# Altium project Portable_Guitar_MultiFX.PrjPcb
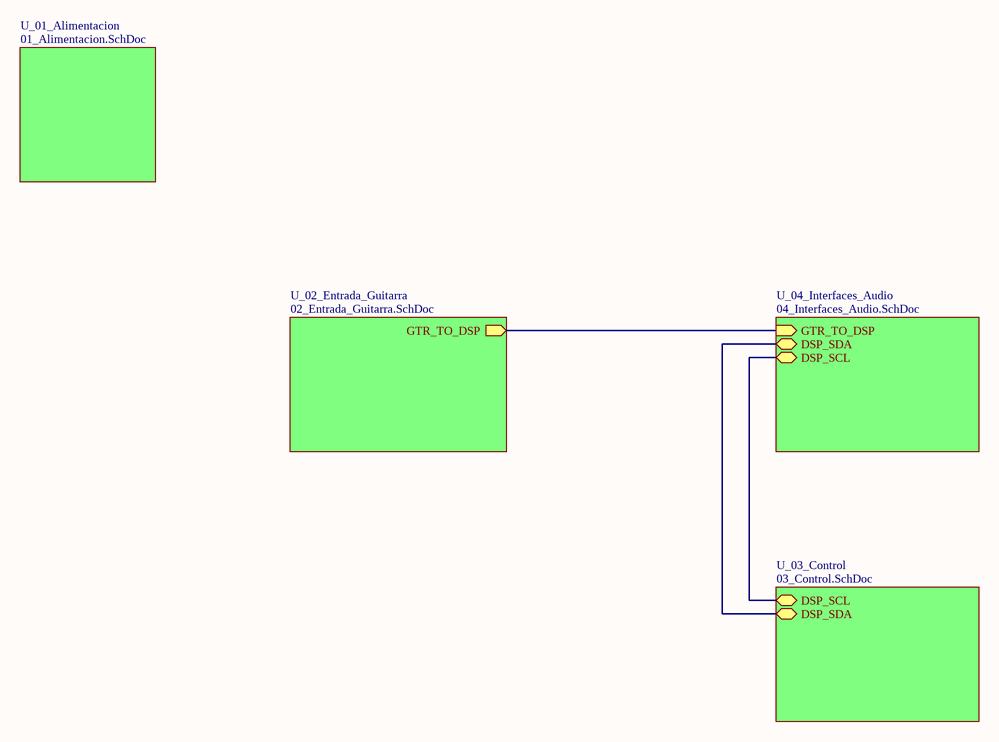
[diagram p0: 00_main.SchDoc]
5 sheets, 67 parts. Net scope: hierarchical (ports join the sheet entries above them; power ports are global).
Board file: Portable_Guitar_MultiFX.PcbDoc
Sheets:
  00_main.SchDoc
    U_02_Entrada_Guitarra = 02_Entrada_Guitarra.SchDoc
    U_04_Interfaces_Audio = 04_Interfaces_Audio.SchDoc
    U_03_Control = 03_Control.SchDoc
    U_01_Alimentacion = 01_Alimentacion.SchDoc

## Sheet 00_main.SchDoc: Portable_Guitar_MultiFX
size A4; Author: Javier Estiven Leon Calderon; Organization: Altium Limited; Address1: L3, 12a Rodborough Rd; Address2: Frenchs Forest; Address3: NSW; Address4: Australia 2086; DocumentNumber: 1; Revision: 1.0; SheetNumber: 1; SheetTotal: 5

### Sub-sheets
U_01_Alimentacion = 01_Alimentacion.SchDoc: no entries
U_02_Entrada_Guitarra = 02_Entrada_Guitarra.SchDoc: GTR_TO_DSP (out)
U_03_Control = 03_Control.SchDoc: DSP_SCL (bidir), DSP_SDA (bidir)
U_04_Interfaces_Audio = 04_Interfaces_Audio.SchDoc: GTR_TO_DSP (in), DSP_SDA (bidir), DSP_SCL (bidir)

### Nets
NetC8_2: sheet U_02_Entrada_Guitarra/GTR_TO_DSP, sheet U_04_Interfaces_Audio/GTR_TO_DSP
NetJP4_2: sheet U_04_Interfaces_Audio/DSP_SCL, sheet U_03_Control/DSP_SCL
NetJP5_2: sheet U_04_Interfaces_Audio/DSP_SDA, sheet U_03_Control/DSP_SDA

## Sheet 02_Entrada_Guitarra.SchDoc: Portable_Guitar_MultiFX
size A4; Organization: Altium Limited; Address1: L3, 12a Rodborough Rd; Address2: Frenchs Forest; Address3: NSW; Address4: Australia 2086; DocumentNumber: 1; Revision: 1.0; SheetNumber: 3; SheetTotal: 5; SPICEModelCachePUIILNWP: <root> / <DocumentId>PUIILNWP</DocumentId> / <CacheFrame Number="0"> / <Model Name="mcp6001" Kind="CKT"> / <Text>.SUBCKT MCP6001 1 2 3 4 5 / *               ¦ ¦ ¦ ¦ ¦ / *               ¦ ¦ ¦ ¦ Output / *               ¦ ¦ ¦ Negative Supply / *               ¦ ¦ Positive Supply / *               ¦ Inverting Input / *               Non-inverting Input / * / ******************************************************************************** / * Software License Agreement                                                   * / *                                                                              * / * The software supplied herewith by Microchip Technology Incorporated (the     * / * "Company") is intended and supplied to you, the Company's customer, for use  * / * soley and exclusively on Microchip products.                                 * / *                                                                              * / * The software is owned by the Company and/or its supplier, and is protected   * / * under applicable copyright laws. All rights are reserved. Any use in         * / * violation of the foregoing restrictions may subject the user to criminal     * / * sanctions under applicable laws, as well as to civil liability for the       * / * breach of the terms and conditions of this license.                          * / *                                                                              * / * THIS SOFTWARE IS PROVIDED IN AN "AS IS" CONDITION. NO WARRANTIES, WHETHER    * / * EXPRESS, IMPLIED OR STATUTORY, INCLUDING, BUT NOT LIMITED TO, IMPLIED        * / * WARRANTIES OF MERCHANTABILITY AND FITNESS FOR A PARTICULAR PURPOSE APPLY TO  * / * THIS SOFTWARE. THE COMPANY SHALL NOT, IN ANY CIRCUMSTANCES, BE LIABLE FOR    * / * SPECIAL, INCIDENTAL OR CONSEQUENTIAL DAMAGES, FOR ANY REASON WHATSOEVER.     * / ******************************************************************************** / * / * Macromodel for the MCP6001/2/4 op amp family: / *   MCP6001, MCP6001R, MCP6001U, MCP6002, MCP6004 / * / * Revision History: / *   REV A: 21-Jun-02, Created model / *   REV B: 16-Jul-02, Improved output stage / *   REV C: 03-Jan-03, Added MCP6001 / *   REV D: 19-Aug-06, Added over temperature, improved output stage, / *                     fixed overdrive recovery time / *   REV E: 27-Jul-07, Updated output impedance for better model stability w/cap load / *   REV F: 09-Jul-12, Added MCP6001R, MCP6001U / * / * Recommendations: / *   Use PSPICE (other simulators may require translation) / *   For a quick, effective design, use a combination of: data sheet / *     specs, bench testing, and simulations with this macromodel / *   For high impedance circuits, set GMIN=100F in .OPTIONS / * / * Supported: / *   Typical performance for temperature range (-40 to 125) degrees Celsius / *   DC, AC, Transient, and Noise analyses. / *   Most specs, including: offsets, DC PSRR, DC CMRR, input impedance, / *     open loop gain, voltage ranges, supply current, ... , etc. / *   Temperature effects for Ibias, Iquiescent, Iout short circuit / *   current, Vsat on both rails, Slew Rate vs. Temp and P.S. / * / * Not Supported: / *   Some Variation in specs vs. Power Supply Voltage / *   Monte Carlo (Vos, Ib), Process variation / *   Distortion (detailed non-linear behavior) / *   Behavior outside normal operating region / * / * Input Stage / V10  3 10 -500M / R10 10 11 6.90K / R11 10 12 6.90K / C11 11 12 0.2p / C12 1  0 6.00P / E12 71 14 POLY(4) 20 0 21 0 26 0 27 0   1.00M 20.1 20.1 1 1 / G12 1 0 62 0 1m / M12 11 14 15 15 NMI L=2.00U W=42.0U / M14 12  2 15 15 NMI L=2.00U W=42.0U / G14 2 0 62 0 1m / C14  2  0 6.00P / I15 15  4 50.0U / V16 16  4 -300M / GD16 16 1 TABLE {V(16,1)} ((-100,-1p)(0,0)(1m,1n)(2m,1m)(3m,1)) / V13  3 13 -300M / GD13 2 13 TABLE {V(2,13)} ((-100,-1p)(0,0)(1m,1n)(2m,1m)(3m,1)) / R70 1 0 20.6T / R71 2 0 20.6T / R72 1 2 20T / I80 1 2 0.5p / * / * Noise, PSRR, and CMRR / I20 21 20 423U / D20 20  0 DN1 / D21  0 21 DN1 / G26  0 26 POLY(1) 3 4   110U -49U / R26 26  0 1 / G27  0 27 POLY(2) 1 0 2 0   -440U 39.7U 39.7U / R27 27  0 1 / * / * Open Loop Gain, Slew Rate / G30  0 30 POLY(1) 12 11   0 1 / R30 30  0 1K / G31  0 31 POLY(1) 3 4 86 5.25 / R31 31  0 1 TC=2.8m / GD31 30 31 TABLE {V(30,31)} ((-11,-1)(-10,-10n)(0,0)(1m,1000)) / G32 32  0 POLY(1) 3 4 113.7 3.5 / R32 32  0 1 TC=2.65m / GD32 30 32 TABLE {V(30,32)} ((-1m,-1000)(0,0)(10,10n)(11,1)) / G33 0 33 30 0 1m / R33 33 0 1k / G34  0 34 33 0 425M / R34  34 0 1K / C34  34 0 74U / G37  0 37 34 0 1m / R37  37 0 1K / C37  37 0 41.6P / G38  0 38 37 0 1m / R38  39 0 1K / L38  38 39 100U / E38  35 0 38 0 1 / G35 33 0 TABLE {V(35,3)} ((-1,-1n)(0,0)(16,1n))(16.1,1)) / G36 33 0 TABLE {V(35,4)} ((-16.1,-1)((-16,-1n)(0,0)(1,1n)) / * / * Output Stage / R80 50 0 100MEG / G50 0 50 57 96 2 / R58 57  96 0.50 / R57 57  0 750 / C58  5  0 2.00P / G57  0 57 POLY(3) 3 0 4 0 35 0   0 0.67M 0.67M 1.5M / GD55 55 57 TABLE {V(55,57)} ((-2m,-1)(-1m,-1m)(0,0)(10,1n)) / GD56 57 56 TABLE {V(57,56)} ((-2m,-1)(-1m,-1m)(0,0)(10,1n)) / E55 55  0 POLY(2) 3 0 51 0 -0.7m 1 -40.0M / E56 56  0 POLY(2) 4 0 52 0 1.2m 1 -37.0M / R51 51 0 1k / R52 52 0 1k / GD51 50 51 TABLE {V(50,51)} ((-10,-1n)(0,0)(1m,1m)(2m,1)) / GD52 50 52 TABLE {V(50,52)} ((-2m,-1)(-1m,-1m)(0,0)(10,1n)) / G53  3  0 POLY(1) 51 0  -49U 1M / G54  0  4 POLY(1) 52 0  -49U -1M / * / * Current Limit / G99 96 5 99 0 1 / R98 0 98 1 TC=-2.8M,2.63U / G97 0 98 TABLE { V(96,5) } ((-11.0,-10.0M)(-1.00M,-9.9M)(0,0)(1.00M,9.9M)(11.0,10.0M)) / E97 99 0 VALUE { V(98)*((V(3)-V(4))*359M + 310M)} / D98 4 5 DESD / D99 5 3 DESD / * / * Temperature / Voltage Sensitive IQuiscent / R61 0 61 100 TC 3.11M 4.51U / G61 3 4 61 0 1 / G60 0 61 TABLE {V(3, 4)} / + ((0,0)(900M,0.0106U)(1.00,0.20U)(1.3,0.63U) / + (1.5,0.66U)(1.6,1.06U)(5.5,1.10U)) / * / * Temp Sensitive offset voltage / I73 0 70 DC 1uA / R74 0 70 1 TC=2 / E75 1 71 70 0 1 / * / * Temp Sensistive IBias / I62 0 62 DC 1uA / R62 0 62 REXP 58.2u / * Voltage on R62 used for G12, G14 in input stage / * / * Models / .MODEL NMI NMOS / .MODEL DESD  D   N=1 IS=1.00E-15 / .MODEL DL  D   N=1 IS=1F / .MODEL DN1 D   IS=1P KF=146E-18 AF=1 / .MODEL REXP RES TCE=10.1 / .ENDS MCP6001</Text> / </Model> / </CacheFrame> / </root>
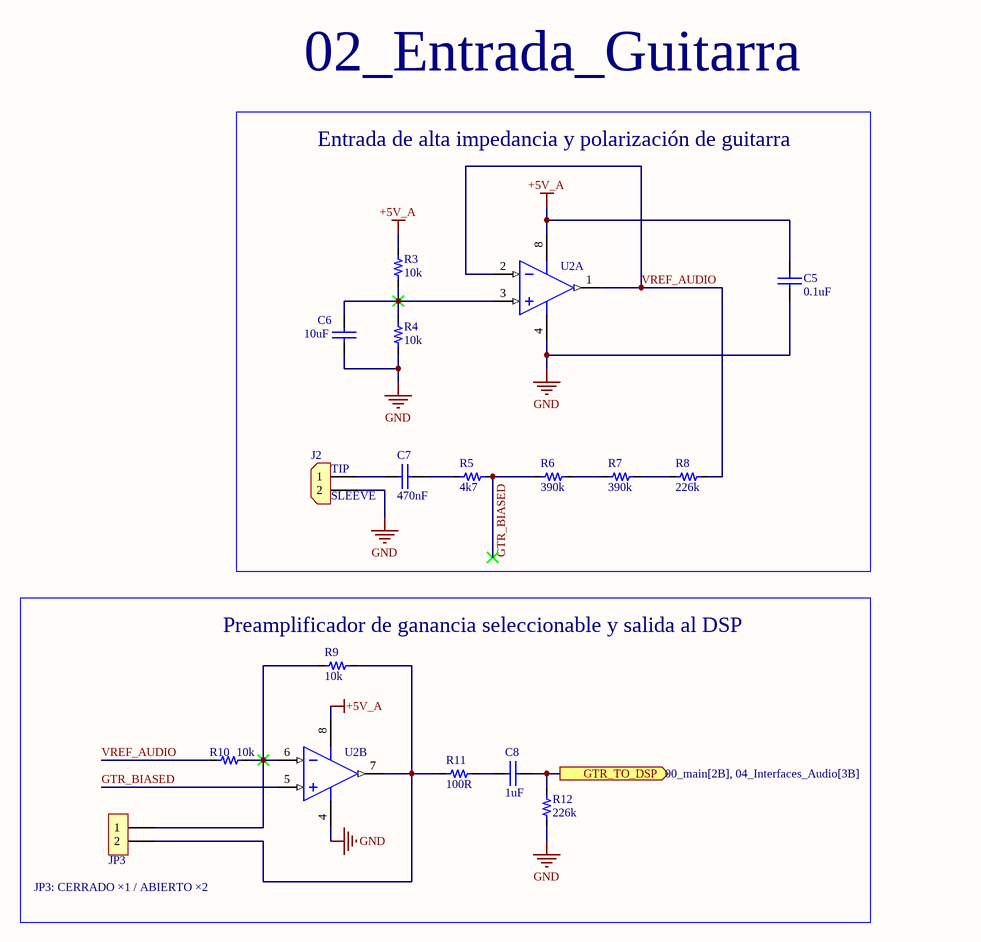
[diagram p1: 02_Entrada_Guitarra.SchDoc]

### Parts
C5  value 0.1uF  [0603_cap]  (hidden comment: 0.1uF 50V)
C6  value 10uF  [0805_cap]  (hidden comment: 10uF 25V)
C7  value 470nF  [0603_cap]  (hidden comment: 470nF 50V)
C8  value 1uF  [0603_cap]  (hidden comment: 1uF 50V)
J2  Connector 2pos  [CON_2x1_TH_5MM]  (value not drawn)
JP3  2x1  [H_2x1_TH_100mil]  (value not drawn)  (no BOM)
R3  value 10k  [0603_res]  (hidden comment: 10k 1/10W)
R4  value 10k  [0603_res]  (hidden comment: 10k 1/10W)
R5  value 4k7  [0603_res]  (hidden comment: 4k7 1/10W)
R6  value 390k  [0603_res]  (hidden comment: 390k 1/10W)
R7  value 390k  [0603_res]  (hidden comment: 390k 1/10W)
R8  value 226k  [0603_res]  (hidden comment: 226k 1/10W)
R9  value 10k  [0603_res]  (hidden comment: 10k 1/10W)
R10  value 10k  [0603_res]  (hidden comment: 10k 1/10W)
R11  value 100R  [0603_res]  (hidden comment: 100R 1/10W)
R12  value 226k  [0603_res]  (hidden comment: 226k 1/10W)
U2  MCP6002-I/P  [PDIP300-P8]  (value not drawn)  (parts A,B of 2)

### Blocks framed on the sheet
Entrada de alta impedancia y polarización de guitarra: C5-C7 J2 R3-R8 U2
Preamplificador de ganancia seleccionable y salida al DSP: C8 JP3 R9-R12 U2

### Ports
GTR_TO_DSP (out, see 00_main[2B], 04_Interfaces_Audio[3B])

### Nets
+5V_A: C5.1 R3.2 U2.8(VDD)
GND: C5.2 C6.2 J2.2 R4.1 R12.1 U2.4(VSS)
GTR_BIASED: R5.2 R6.1 U2.5(VINB+)
VREF_AUDIO: R8.2 R10.1 U2.1(VOUTA) U2.2(VINA-)
NetC6_1: C6.1 R3.1 R4.2 U2.3(VINA+)
NetC7_1: C7.1 J2.1
NetC7_2: C7.2 R5.1
NetC8_1: C8.1 R11.2
NetC8_2: C8.2 R12.2 ; port GTR_TO_DSP
NetJP3_1: JP3.1 R9.1 R10.2 U2.6(VINB-)
NetJP3_2: JP3.2 R9.2 R11.1 U2.7(VOUTB)
NetR6_2: R6.2 R7.1
NetR7_2: R7.2 R8.1

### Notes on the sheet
- 02_Entrada_Guitarra
- (near J2) TIP
- (near J2) SLEEVE
- (near JP3) JP3: CERRADO ×1 / ABIERTO ×2

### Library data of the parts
C5 = Cap_0.1uF_0603_50V: 50V 100nF Y5V -20%~+80% 0603 Multilayer Ceramic Capacitors MLCC - SMD/SMT ROHS; Manufacturer: Walsin Tech Corp; Manufacturer Part Number: 0603F104Z500CT
C6 = Cap_10uF_0805_25V_: 25V 10uF X5R ±10% 0805 Multilayer Ceramic Capacitors MLCC - SMD/SMT ROHS; Manufacturer: Samsung Electro-Mechanics; Manufacturer Part Number: CL21A106KAYNNNE
C7 = Cap_470nF_0603_50V: 50V 470nF X7R ±10% 0603 Multilayer Ceramic Capacitors MLCC - SMD/SMT ROHS; Manufacturer: Chinocera; Manufacturer Part Number: HGC0603R7474K500NTHJ
C8 = Cap_1uF_0603_50V: 50V 1uF X5R ±10% 0603 Multilayer Ceramic Capacitors MLCC - SMD/SMT ROHS; Manufacturer: Samsung Electro-Mechanics; Manufacturer Part Number: CL10A105KB8NNNC
J2 = Con_2x1_TH_5mm: 2POS 5MM; Manufacturer: JILN; Manufacturer Part Number: JL126-50002G01
JP3 = H_Male_2x1_TH_100mil
R3 R4 R9 R10 = Res_10k_0603_1/10W: RES SMD 10k OHM 5% 1/10W 0603; Manufacturer: FOJAN; Manufacturer Part Number: FRC0603J103TS
R5 = Res_4k7_0603_1/10W: 100mW Thick Film Resistor 75V ±1% 4.7kΩ 0603 Chip Resistor - Surface Mount ROHS; Manufacturer: VO; Manufacturer Part Number: SCR0603F4K7
R6 R7 = Res_390k_0603_1/10W: 100mW Thick Film Resistor 75V ±100ppm/℃ ±1% 390kΩ 0603 Chip Resistor - Surface Mount ROHS; Manufacturer: YAGEO; Manufacturer Part Number: RC0603FR-07390KL
R8 R12 = Res_226k_0603_1/10W: 100mW Thick Film Resistors 75V ±100ppm/℃ ±1% 226kΩ 0603 Chip Resistor - Surface Mount ROHS; Manufacturer: YAGEO; Manufacturer Part Number: RC0603FR-07226KL
R11 = Res_100R_0603_1/10W: RES SMD 100R OHM 5% 1/10W 0603; Manufacturer: FOJAN; Manufacturer Part Number: FRC0603J101 TS
U2 = CMP-0187-00119-3: None; Max Frequency: 1kHz; Operating Supply Current: 100uA; Amplifier Type: GENERAL PURPOSE; Number of Channels: 2; Power Supply Rejection Ratio (PSRR): 86dB; Max Input Voltage: 6V; Bandwidth: 1MHz; Voltage Gain: 112dB; Input Bias Current: 1pA; Slew Rate-Nom: 0.6V/µs; Output Current: 23mA; Input Offset Voltage-Max: 4.5mV; Common Mode Rejection Ratio: 60dB; Min Input Voltage: 1.8V; Operating Supply Voltage: 5.5V

## Sheet 04_Interfaces_Audio.SchDoc: Portable_Guitar_MultiFX
size A4; Organization: Altium Limited; Address1: L3, 12a Rodborough Rd; Address2: Frenchs Forest; Address3: NSW; Address4: Australia 2086; DocumentNumber: 1; SheetNumber: 5; SheetTotal: 5
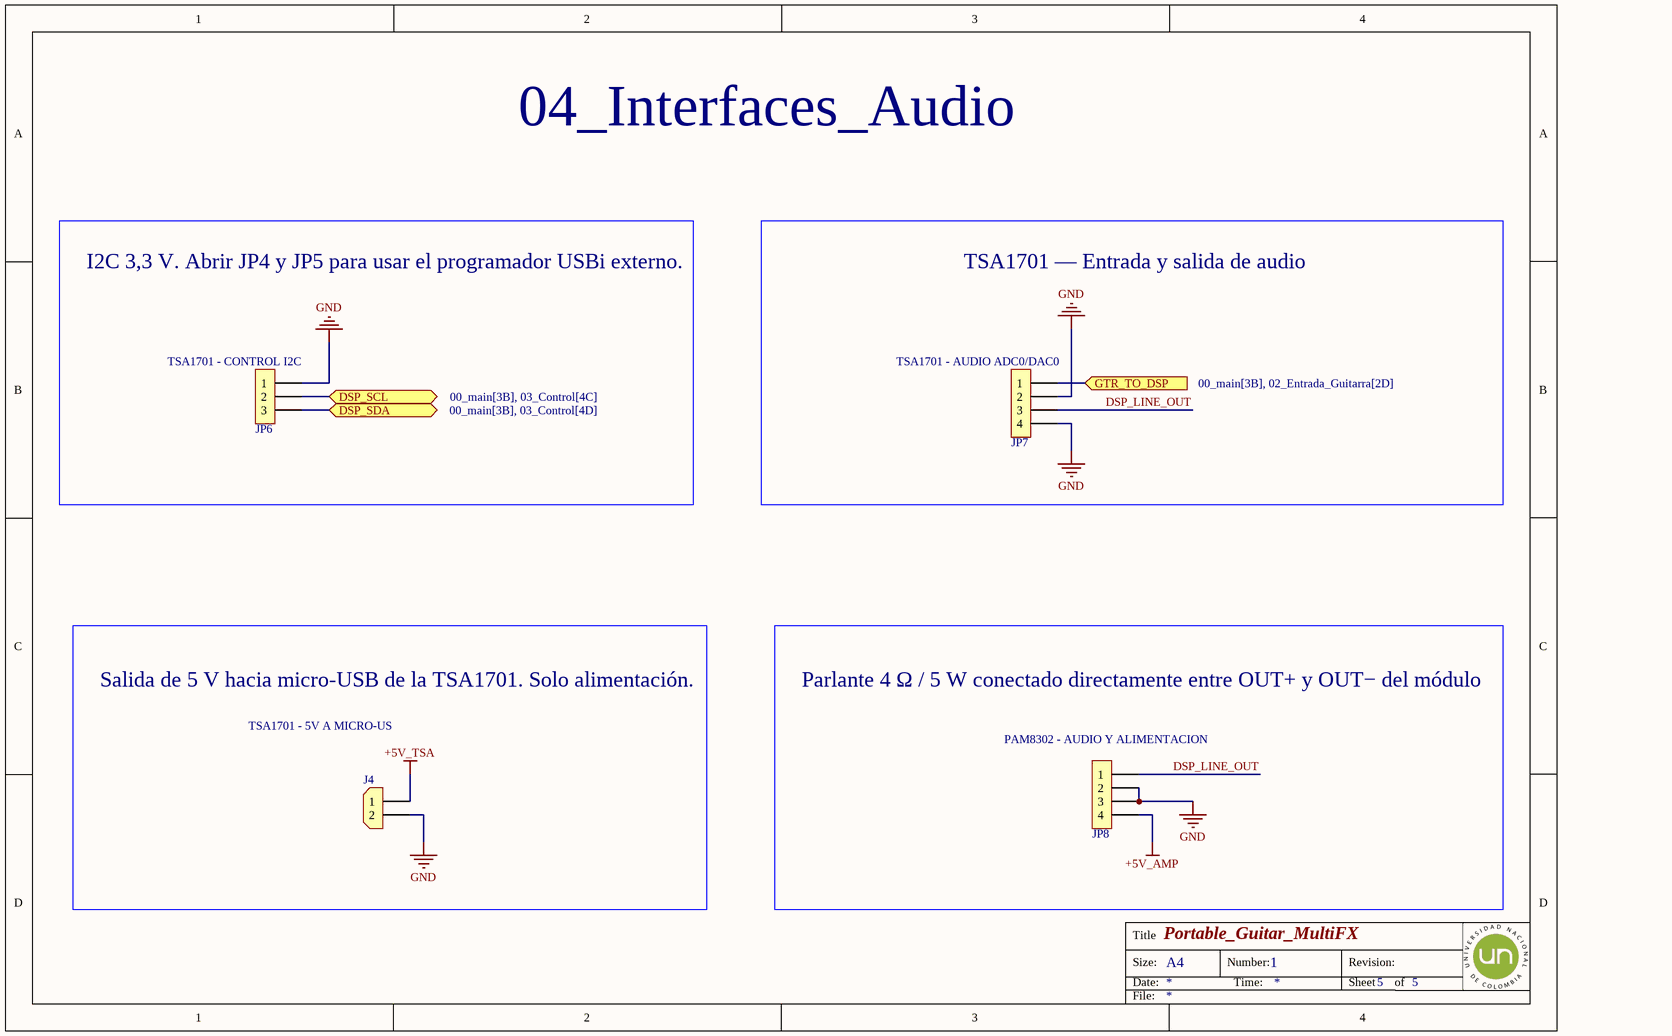
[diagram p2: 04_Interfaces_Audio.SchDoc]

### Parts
J4  TSA1701 - 5V A MICRO-US  [CON_2x1_TH_2MM]
JP6  TSA1701 - CONTROL I2C  [H_3X1_TH_100mil]  (no BOM)
JP7  TSA1701 - AUDIO ADC0/DAC0  [H_4x1_TH_2.54mm]  (no BOM)
JP8  PAM8302 - AUDIO Y ALIMENTACION  [H_4x1_TH_2.54mm]  (no BOM)

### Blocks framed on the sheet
TSA1701 — Entrada y salida de audio: JP7

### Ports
DSP_SCL (bidir, see 00_main[3B], 03_Control[4C]), DSP_SDA (bidir, see 00_main[3B], 03_Control[4D]), GTR_TO_DSP (in, see 00_main[3B], 02_Entrada_Guitarra[2D])

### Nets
+5V_AMP: JP8.4
+5V_TSA: J4.1
GND: J4.2 JP6.1 JP7.2 JP7.4 JP8.2 JP8.3
DSP_LINE_OUT: JP7.3 JP8.1
NetC8_2: JP7.1 ; port GTR_TO_DSP
NetJP4_2: JP6.2 ; port DSP_SCL
NetJP5_2: JP6.3 ; port DSP_SDA

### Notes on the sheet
- 04_Interfaces_Audio
- I2C 3,3 V. Abrir JP4 y JP5 para usar el programador USBi externo.
- Salida de 5 V hacia micro-USB de la TSA1701. Solo alimentación.
- Parlante 4 Ω / 5 W conectado directamente entre OUT+ y OUT− del módulo

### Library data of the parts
J4 = Con_2x1_TH_JST_2MM: 2POS 2MM; Manufacturer: JST; Manufacturer Part Number: S2B-PH-K-S(LF)(SN)
JP6 = H_Male_3x1_TH_100mil
JP7 JP8 = H_Male_4x1_TH_100mil

## Sheet 03_Control.SchDoc: Portable_Guitar_MultiFX
size 420 x 297 mm; Organization: Altium Limited; Address1: L3, 12a Rodborough Rd; Address2: Frenchs Forest; Address3: NSW; Address4: Australia 2086; DocumentNumber: 1; Revision: 1.0; SheetNumber: 4; SheetTotal: 5
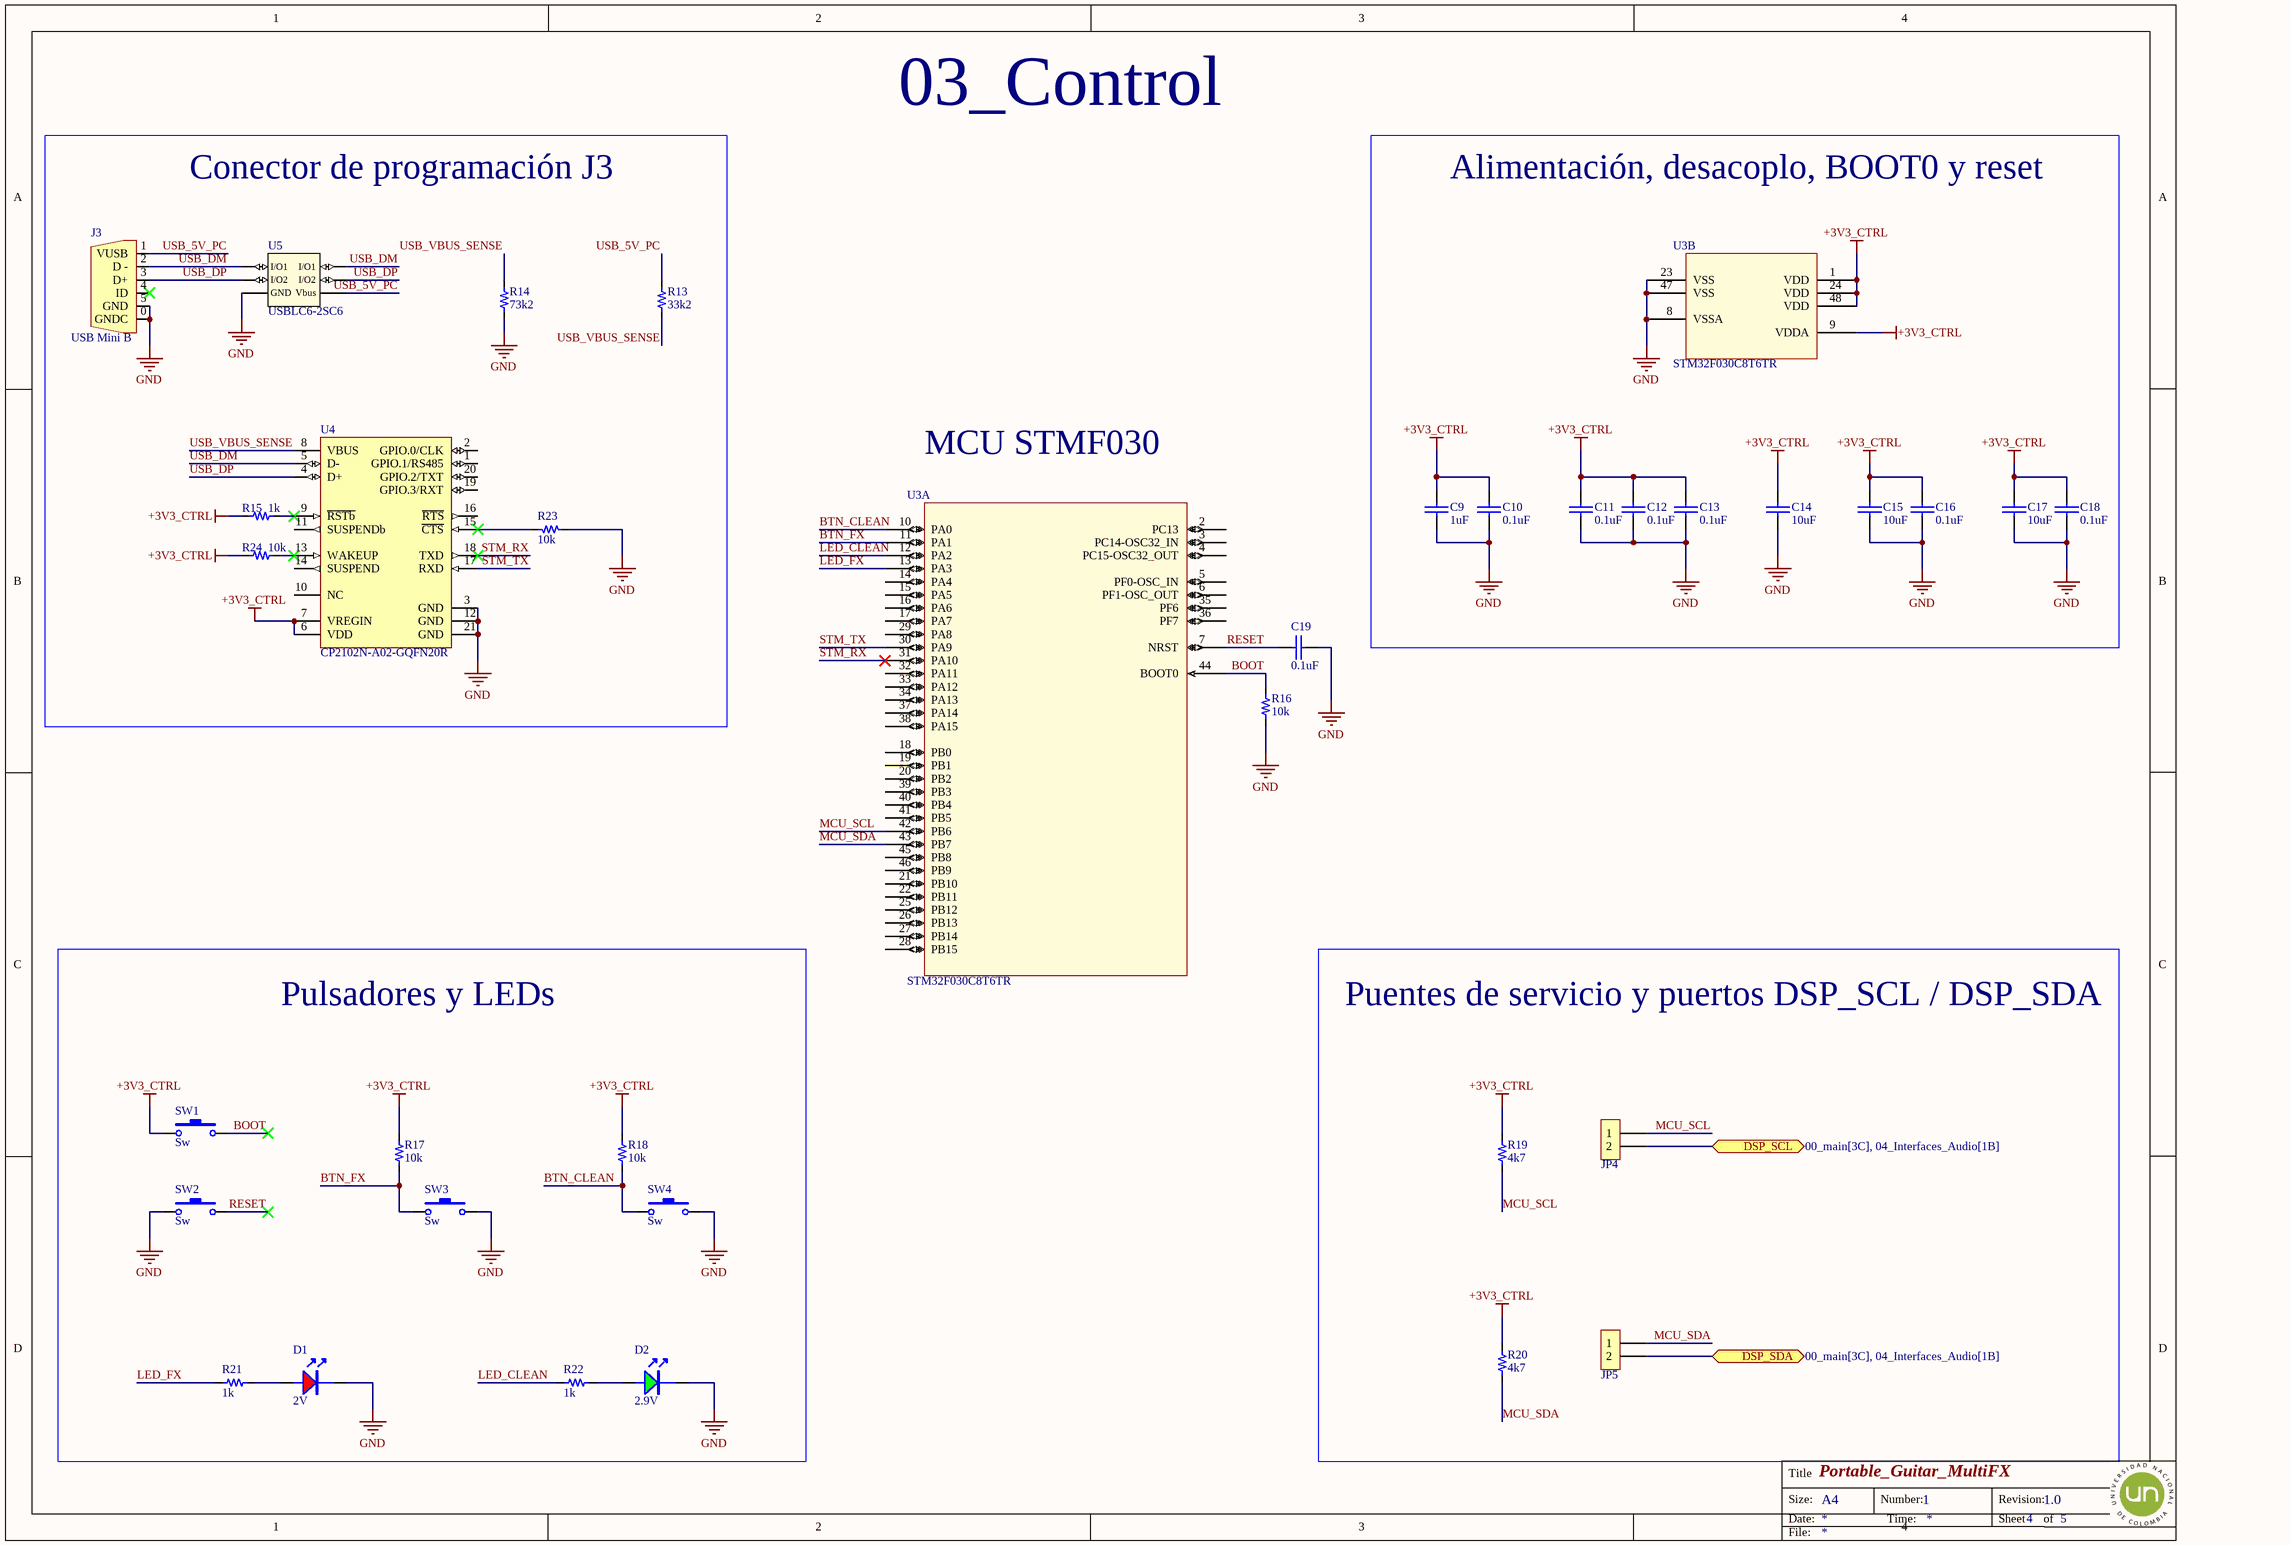
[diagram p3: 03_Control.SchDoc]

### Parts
C9  value 1uF  [0603_cap]  (hidden comment: 1uF 50V)
C10  value 0.1uF  [0603_cap]  (hidden comment: 0.1uF 50V)
C11  value 0.1uF  [0603_cap]  (hidden comment: 0.1uF 50V)
C12  value 0.1uF  [0603_cap]  (hidden comment: 0.1uF 50V)
C13  value 0.1uF  [0603_cap]  (hidden comment: 0.1uF 50V)
C14  value 10uF  [0603_cap]  (hidden comment: 10uF 10V)
C15  value 10uF  [0603_cap]  (hidden comment: 10uF 10V)
C16  value 0.1uF  [0603_cap]  (hidden comment: 0.1uF 50V)
C17  value 10uF  [0603_cap]  (hidden comment: 10uF 10V)
C18  value 0.1uF  [0603_cap]  (hidden comment: 0.1uF 50V)
C19  value 0.1uF  [0603_cap]  (hidden comment: 0.1uF 50V)
D1  2V  [0805_LED]
D2  2.9V  [0805_LED]
J3  USB Mini B  [CON_5x1_SMD_miniUSB_B]
JP4  2x1  [H_2x1_TH_100mil]  (value not drawn)  (no BOM)
JP5  2x1  [H_2x1_TH_100mil]  (value not drawn)  (no BOM)
R13  value 33k2  [0603_res]  (hidden comment: 33k2 1/10W)
R14  value 73k2  [0603_res]  (hidden comment: 73k2 1/10W)
R15  value 1k  [0603_res]  (hidden comment: 1k 1/10W)
R16  value 10k  [0603_res]  (hidden comment: 10k 1/10W)
R17  value 10k  [0603_res]  (hidden comment: 10k 1/10W)
R18  value 10k  [0603_res]  (hidden comment: 10k 1/10W)
R19  value 4k7  [0603_res]  (hidden comment: 4k7 1/10W)
R20  value 4k7  [0603_res]  (hidden comment: 4k7 1/10W)
R21  value 1k  [0603_res]  (hidden comment: 1k 1/10W)
R22  value 1k  [0603_res]  (hidden comment: 1k 1/10W)
R23  value 10k  [0603_res]  (hidden comment: 10k 1/10W)
R24  value 10k  [0603_res]  (hidden comment: 10k 1/10W)
SW1  Sw  [Sw_PUSH_4.5x4.5x5mm]
SW2  Sw  [Sw_PUSH_4.5x4.5x5mm]
SW3  Sw  [Sw_PUSH_4.5x4.5x5mm]
SW4  Sw  [Sw_PUSH_4.5x4.5x5mm]
U3  STM32F030C8T6TR  [LQFP48_7x7mm]  (parts A,B of 2)
U4  CP2102N-A02-GQFN20R  [WFQFN_20_EP_3X3MM]
U5  USBLC6-2SC6  [SOT_23_6]

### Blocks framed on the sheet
Conector de programación J3: J3 R13-R15 R23 R24 U4 U5
Alimentación, desacoplo, BOOT0 y reset: C9-C18 U3
Pulsadores y LEDs: D1 D2 R17 R18 R21 R22 SW1-SW4
Puentes de servicio y puertos DSP_SCL / DSP_SDA: JP4 JP5 R19 R20

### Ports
DSP_SCL (bidir, see 00_main[3C], 04_Interfaces_Audio[1B]), DSP_SDA (bidir, see 00_main[3C], 04_Interfaces_Audio[1B])

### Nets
+3V3_CTRL: C9.1 C10.1 C11.1 C12.2 C13.2 C14.1 C15.1 C16.1 C17.1 C18.1 R15.1 R17.2 R18.2 R19.2 R20.2 R24.1 SW1.1 U3.1(VDD) U3.9(VDDA) U3.24(VDD) U3.48(VDD) U4.6(VDD) U4.7(VREGIN)
GND: C9.2 C10.2 C11.2 C12.1 C13.1 C14.2 C15.2 C16.2 C17.2 C18.2 C19.2 D1.2 D2.2 J3.0(GNDC) J3.5(GND) R14.1 R16.1 R23.1 SW2.1 SW3.2 SW4.2 U3.8(VSSA) U3.23(VSS) U3.47(VSS) U4.3(GND) U4.12(GND) U4.21(GND) U5.2(GND)
BOOT: R16.2 SW1.2 U3.44(BOOT0)
BTN_CLEAN: R18.1 SW4.1 U3.10(PA0)
BTN_FX: R17.1 SW3.1 U3.11(PA1)
LED_CLEAN: R22.1 U3.12(PA2)
LED_FX: R21.1 U3.13(PA3)
MCU_SCL: JP4.1 R19.1 U3.42(PB6)
MCU_SDA: JP5.1 R20.1 U3.43(PB7)
RESET: C19.1 SW2.2 U3.7(NRST)
STM_RX: U3.31(PA10) U4.18(TXD)
STM_TX: U3.30(PA9) U4.17(RXD)
USB_5V_PC: J3.1(VUSB) R13.2 U5.5(Vbus)
USB_DM: J3.2(D_-) U4.5(D-) U5.1(I/O1) U5.6(I/O1)
USB_DP: J3.3(D+) U4.4(D+) U5.3(I/O2) U5.4(I/O2)
USB_VBUS_SENSE: R13.1 R14.2 U4.8(VBUS)
NetD1_1: D1.1(A) R21.2
NetD2_1: D2.1(A) R22.2
NetJP4_2: JP4.2 ; port DSP_SCL
NetJP5_2: JP5.2 ; port DSP_SDA
NetR15_2: R15.2 U4.9(~{RSTb})
NetR23_2: R23.2 U4.15(~{CTS})
NetR24_2: R24.2 U4.13(WAKEUP)

Not connected (* = marked no-connect by the designer): J3 4(ID)*; U3 2(PC13) 3(PC14-OSC32_IN) 4(PC15-OSC32_OUT) 5(PF0-OSC_IN) 6(PF1-OSC_OUT) 14(PA4) 15(PA5) 16(PA6) 17(PA7) 18(PB0) 19(PB1) 20(PB2) 21(PB10) 22(PB11) 25(PB12) 26(PB13) 27(PB14) 28(PB15) 29(PA8) 32(PA11) 33(PA12) 34(PA13) 35(PF6) 36(PF7) 37(PA14) 38(PA15) 39(PB3) 40(PB4) 41(PB5) 45(PB8) 46(PB9); U4 1(GPIO.1/RS485) 2(GPIO.0/CLK) 10(NC) 11(SUSPENDb) 14(SUSPEND) 16(~{RTS}) 19(GPIO.3/RXT) 20(GPIO.2/TXT)

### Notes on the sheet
- 03_Control
- MCU STMF030

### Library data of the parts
C9 = Cap_1uF_0603_50V: as C8 on sheet 02_Entrada_Guitarra
C10-C13 C16 C18 C19 = Cap_0.1uF_0603_50V: as C5 on sheet 02_Entrada_Guitarra
C14 C15 C17 = Cap_10uF_0603_10V: 10V 10uF X5R ±10% 0603 Multilayer Ceramic Capacitors MLCC - SMD/SMT ROHS; Manufacturer: CCTC; Manufacturer Part Number: TCC0603X5R106K100CT
D1 = LED_0805_RED: LED RED CLEAR 0805 SMD; Manufacturer: XINGLIGHT; Manufacturer Part Number: XL-2012SURC
D2 = LED_0805_Green: LED GREEN CLEAR 0805 SMD; Manufacturer: XINGLIGHT; Manufacturer Part Number: XL-2012UGC
J3 = Con_Mini_USB_B: CONN RCPT USB2.0 MINI B SMD R/A; Manufacturer Part Number: KH-MINI-SMT-5P-Cu; Manufacturer: EDAC Inc.
JP4 JP5 = H_Male_2x1_TH_100mil
R13 = Res_33k2_0603_1/10W: 100mW Thick Film Resistor 75V ±100ppm/℃ ±1% 33.2kΩ 0603 Chip Resistor - Surface Mount ROHS; Manufacturer: YAGEO; Manufacturer Part Number: RC0603FR-0733K2L
R14 = Res_73k2_0603_1/10W: 100mW Thick Film Resistor 75V ±100ppm/℃ ±1% 73.2kΩ 0603 Chip Resistor - Surface Mount ROHS; Manufacturer: YAGEO; Manufacturer Part Number: RC0603FR-0773K2L
R15 R21 R22 = Res_1k_0603_1/10W: RES SMD 1k OHM 5% 1/10W 0603; Manufacturer: FOJAN; Manufacturer Part Number: FRC0603J102 TS
R16-R18 R23 R24 = Res_10k_0603_1/10W: as R3 on sheet 02_Entrada_Guitarra
R19 R20 = Res_4k7_0603_1/10W: as R5 on sheet 02_Entrada_Guitarra
SW1-SW4 = Sw_PUSH_4.5x4.5x5.0xmm: SWITCH TACTILE SPST-NO 0.05A 12V; Manufacturer: BZCN; Manufacturer Part Number: TSC015A05026A
U3 = IC_STM32F030C8T6TR_LQFP48_7x7MM: IC MCU 32BIT 64KB FLASH 48LQFP; Manufacturer: STMicroelectronics
U4 = IC_SGL_USB2UART-BRIDGE_20QFN: IC USB TO UART BRIDGE QFN20; Manufacturer: Silicon Labs
U5 = TVS_5.25V_2CH_SOT_23_6: TVS DIODE 5.25V 17V SOT23-6; Manufacturer: STMicroelectronics

## Sheet 01_Alimentacion.SchDoc: Portable_Guitar_MultiFX
size A4; Organization: Altium Limited; Address1: L3, 12a Rodborough Rd; Address2: Frenchs Forest; Address3: NSW; Address4: Australia 2086; DocumentNumber: 1; Revision: 1.0; SheetNumber: 2; SheetTotal: 5
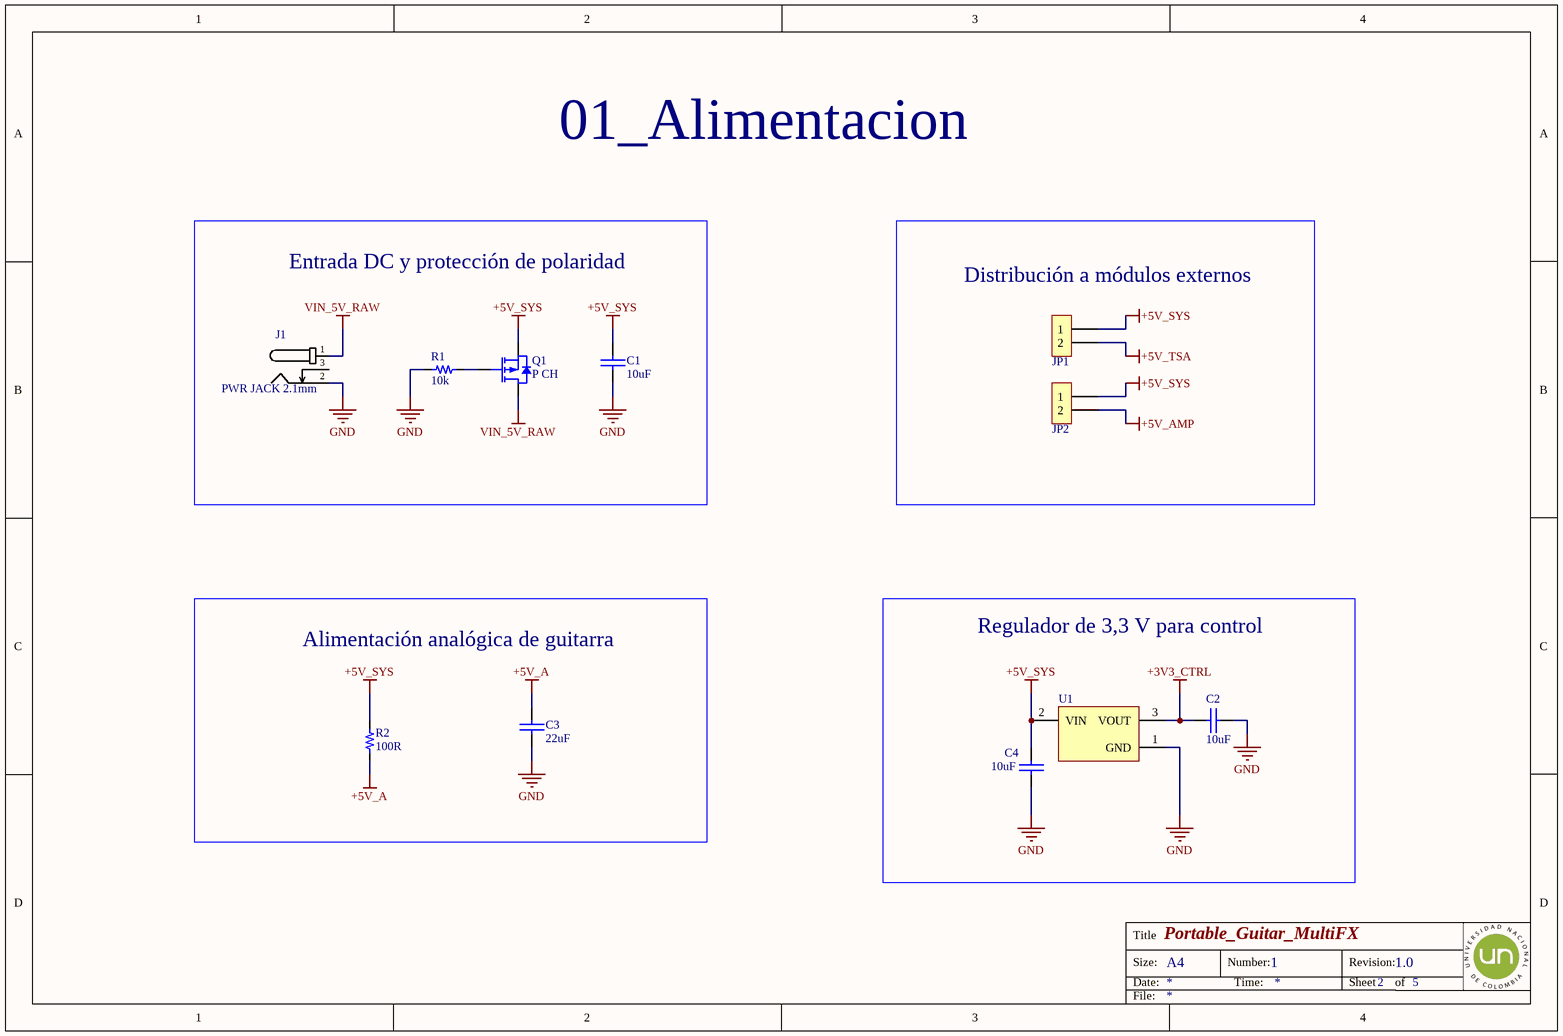
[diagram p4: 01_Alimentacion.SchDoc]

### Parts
C1  value 10uF  [0805_cap]  (hidden comment: 10uF 25V)
C2  value 10uF  [0805_cap]  (hidden comment: 10uF 25V)
C3  value 22uF  [0805_cap]  (hidden comment: 22uF 16V)
C4  value 10uF  [0805_cap]  (hidden comment: 10uF 25V)
J1  PWR JACK 2.1mm  [CON_POWER_BARREL_2.1MM_3CONN]
JP1  2x1  [H_2x1_TH_100mil]  (value not drawn)  (no BOM)
JP2  2x1  [H_2x1_TH_100mil]  (value not drawn)  (no BOM)
Q1  P CH  [SOT_23_3]
R1  value 10k  [0603_res]  (hidden comment: 10k 1/10W)
R2  value 100R  [0603_res]  (hidden comment: 100R 1/10W)
U1  MCP1700-3302E/TO  [TO-92-TO3]  (value not drawn)

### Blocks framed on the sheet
Entrada DC y protección de polaridad: C1 J1 Q1 R1
Distribución a módulos externos: JP1 JP2
Alimentación analógica de guitarra: C3 R2
Regulador de 3,3 V para control: C2 C4 U1

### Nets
+3V3_CTRL: C2.2 U1.3(VOUT)
+5V_A: C3.1 R2.1
+5V_AMP: JP2.2
+5V_SYS: C1.1 C4.2 JP1.1 JP2.1 Q1.2(S) R2.2 U1.2(VIN)
+5V_TSA: JP1.2
GND: C1.2 C2.1 C3.2 C4.1 J1.2 R1.1 U1.1(GND)
VIN_5V_RAW: J1.1 Q1.3(D)
NetQ1_1: Q1.1(G) R1.2

Not connected (* = marked no-connect by the designer): J1 3

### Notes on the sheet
- 01_Alimentacion

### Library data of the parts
C1 C2 C4 = Cap_10uF_0805_25V_: as C6 on sheet 02_Entrada_Guitarra
C3 = Cap_22uF_0805_16V: 16V 22uF X5R ±20% 0805 Multilayer Ceramic Capacitors MLCC - SMD/SMT ROHS; Manufacturer: Chinocera; Manufacturer Part Number: HGC0805R5226M160NSLJ
J1 = Con_Power_Jack_2.1mm_3pins: CONN PWR JACK 2X5.5MM SOLDER; Manufacturer: HCTL; Manufacturer Part Number: HC-DC-005-2.0T
JP1 JP2 = H_Male_2x1_TH_100mil
Q1 = Q_PFET_30V_3A_SOT23: MOSFET P-CH 20V 3A SOT23; Manufacturer: ALLPOWER(ShenZhen Quan Li Semiconductor); Manufacturer Part Number: AP2301
R1 = Res_10k_0603_1/10W: as R3 on sheet 02_Entrada_Guitarra
R2 = Res_100R_0603_1/10W: as R11 on sheet 02_Entrada_Guitarra
U1 = CMP-0136-00007-1: Low Quiescent Current LDO, 3-Pin TO-92, Extended TemperatureBAG

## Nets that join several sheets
+3V3_CTRL: 03_Control (23 pins), 01_Alimentacion (C2.2 U1.3)
+5V_A: 02_Entrada_Guitarra (C5.1 R3.2 U2.8), 01_Alimentacion (C3.1 R2.1)
+5V_AMP: 04_Interfaces_Audio (JP8.4), 01_Alimentacion (JP2.2)
+5V_TSA: 04_Interfaces_Audio (J4.1), 01_Alimentacion (JP1.2)
GND: 02_Entrada_Guitarra (6 pins), 04_Interfaces_Audio (6 pins), 03_Control (28 pins), 01_Alimentacion (7 pins)
NetC8_2: 02_Entrada_Guitarra (C8.2 R12.2), 04_Interfaces_Audio (JP7.1)
NetJP4_2: 04_Interfaces_Audio (JP6.2), 03_Control (JP4.2)
NetJP5_2: 04_Interfaces_Audio (JP6.3), 03_Control (JP5.2)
